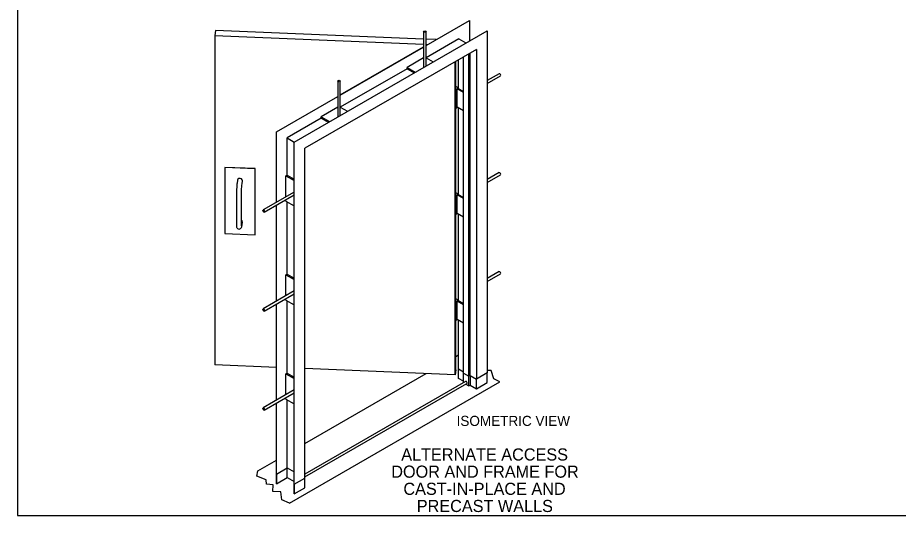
# Model space of a CAD drawing. Extents: x 99862 to 103151, y 100000 to 105076.
# Drawn here: x 99862 to 101604, y 100000 to 100986 of the extents above; entities that cross this region are included whole.
import ezdxf

# ---------------------------------------------------------------- set-up
doc = ezdxf.new("R2010")
doc.units = 0
for name, color, linetype in [('Level 1', 7, 'Continuous'), ('Level 18', 7, 'Continuous'), ('Level 20', 7, 'Continuous'), ('Level 5', 7, 'Continuous'), ('Level 60', 7, 'Continuous')]:
    doc.layers.add(name, color=color, linetype=linetype)

msp = doc.modelspace()

# ---------------------------------------------------------------- linework, layer by layer
at = {"layer": 'Level 1'}
for p, q in [((100395.1, 100673.5), (100392.6, 100672.1)), ((100373.9, 100227.7), (100373.9, 100418)), ((100374.2, 100227.9), (100374.2, 100418.2)), ((100392.6, 100426.1), (100392.6, 100428.8)), ((100392.6, 100426.1), (100408.9, 100416.7)), ((100373.9, 100081.6), (100373.9, 100221.9)), ((100374.2, 100081.4), (100374.2, 100222.1)), ((100409.2, 100061.2), (100430.4, 100073.5)), ((100408.9, 100061.4), (100409.2, 100061.2))]:
    msp.add_line(p, q, dxfattribs=at)
msp.add_lwpolyline([(99862, 99999.5), (103151, 99999.5), (103151, 102075.5), (99862, 102075.5)], close=True, dxfattribs=at)
at = {"layer": 'Level 18'}
for p, q in [((100670.2, 100930.4), (100755.7, 100979.8)), ((100670.2, 100930), (100756, 100979.6)), ((100756, 100979.6), (100755.7, 100979.8)), ((100756, 100979.6), (100756, 100939.6)), ((100253.2, 100960), (100252, 100949.9)), ((100665.2, 100942.9), (100253.2, 100960)), ((100408.9, 100739.1), (100790.7, 100959.6)), ((100409.2, 100738.9), (100791, 100959.4)), ((100665.2, 100957.9), (100665.2, 100887.1)), ((100670.2, 100890), (100670.2, 100957.9)), ((100790.7, 100959.6), (100791, 100959.4)), ((100791, 100959.4), (100791, 100281.7)), ((100252, 100949.9), (100665.2, 100932.8)), ((100252, 100949.9), (100252, 100297.8)), ((100735.2, 100943.4), (100670.2, 100905.9)), ((100690.1, 100941.9), (100670.2, 100942.7)), ((100735.2, 100943.4), (100749, 100935.5)), ((100769.8, 100922.6), (100430.4, 100726.7)), ((100500.4, 100832.4), (100665.2, 100927.5)), ((100500.4, 100832), (100665.2, 100927.1)), ((100670.2, 100932.6), (100673.7, 100932.4)), ((100769.8, 100922.6), (100769.8, 100269.4)), ((100665.2, 100905.9), (100632.4, 100887)), ((100670.2, 100906), (100684, 100898)), ((100744.2, 100281.2), (100744.2, 100907.8)), ((100754.8, 100275), (100754.8, 100913.9)), ((100757.5, 100276.6), (100757.5, 100915.5)), ((100727.5, 100278), (100727.5, 100898.2)), ((100728.8, 100288.1), (100728.8, 100898.9)), ((100734.5, 100845.1), (100734.5, 100902.2)), ((100632.4, 100884.1), (100500.4, 100807.9)), ((100632.4, 100884.1), (100632.4, 100887)), ((100632.4, 100887), (100648.7, 100877.6)), ((100632.4, 100884.1), (100646.2, 100876.1)), ((100814.9, 100874.4), (100791, 100860.6)), ((100495.4, 100859.9), (100495.4, 100789.1)), ((100500.4, 100792), (100500.4, 100859.9)), ((100791, 100854.8), (100817.4, 100870)), ((100728.8, 100843.9), (100727.5, 100833.3)), ((100744.2, 100837.4), (100731.8, 100844.5)), ((100731.8, 100807.8), (100731.8, 100844.5)), ((100732.9, 100846), (100744.2, 100839.4)), ((100373.9, 100759.3), (100495.4, 100829.5)), ((100374.2, 100759.1), (100495.4, 100829.1)), ((100495.4, 100807.9), (100462.7, 100789)), ((100500.4, 100808), (100514.3, 100800)), ((100728.9, 100807.3), (100727.5, 100796.5)), ((100744.2, 100800.7), (100731.8, 100807.8)), ((100734.5, 100634.8), (100734.5, 100806.3)), ((100462.8, 100786.2), (100395.1, 100747.1)), ((100462.7, 100789), (100479, 100779.6)), ((100462.7, 100786.1), (100462.7, 100789)), ((100462.7, 100786.3), (100476.6, 100778.2)), ((100373.9, 100619.7), (100373.9, 100759.3)), ((100374.2, 100759.1), (100373.9, 100759.3)), ((100374.2, 100619.9), (100374.2, 100759.1)), ((100395.1, 100747.1), (100408.9, 100739.1)), ((100395.1, 100673.5), (100395.1, 100747.1)), ((100408.9, 100061.4), (100408.9, 100739.1)), ((100408.9, 100739.1), (100409.2, 100738.9)), ((100409.2, 100061.2), (100409.2, 100738.9)), ((100430.4, 100073.5), (100430.4, 100726.7)), ((100271.9, 100688.6), (100271.9, 100688.9)), ((100331.8, 100686.4), (100271.9, 100688.9)), ((100271.9, 100688.6), (100271.9, 100557.9)), ((100331.7, 100686.1), (100271.9, 100688.6)), ((100331.7, 100686.1), (100331.8, 100686.4)), ((100331.7, 100555.5), (100331.7, 100686.1)), ((100331.8, 100555.7), (100331.8, 100686.4)), ((100296.9, 100663.5), (100296.1, 100657.7)), ((100306.1, 100656.5), (100306.8, 100662.2)), ((100392.6, 100672.1), (100408.9, 100662.7)), ((100392.6, 100630.5), (100392.6, 100672.1)), ((100395.1, 100673.5), (100408.9, 100665.5)), ((100814.9, 100678.4), (100791, 100664.6)), ((100791, 100658.9), (100817.4, 100674.1)), ((100294.7, 100629.2), (100294.7, 100580.2)), ((100304.7, 100580.2), (100304.7, 100629.2)), ((100408.9, 100639.9), (100347.5, 100604.5)), ((100350, 100600.2), (100408.9, 100634.2)), ((100728.9, 100633.8), (100727.5, 100623)), ((100744.2, 100627.2), (100731.8, 100634.3)), ((100731.8, 100597.6), (100731.8, 100634.3)), ((100732.9, 100635.7), (100744.2, 100629.2)), ((100373.9, 100423.8), (100373.9, 100614)), ((100374.2, 100424), (100374.2, 100614.2)), ((100392.6, 100622.1), (100392.6, 100624.8)), ((100392.6, 100622.1), (100408.9, 100612.7)), ((100395.1, 100477.6), (100395.1, 100620.6)), ((100728.9, 100597.1), (100727.5, 100586.3)), ((100744.2, 100590.4), (100731.8, 100597.6)), ((100734.5, 100424.6), (100734.5, 100596)), ((100306.1, 100574.8), (100306.8, 100580.6)), ((100271.9, 100557.9), (100331.7, 100555.5)), ((100331.7, 100555.5), (100331.8, 100555.7)), ((100395.1, 100477.6), (100392.6, 100476.1)), ((100392.6, 100476.1), (100408.9, 100466.7)), ((100392.6, 100434.6), (100392.6, 100476.1)), ((100395.1, 100477.6), (100408.9, 100469.6)), ((100814.9, 100482.3), (100791, 100468.5)), ((100791, 100462.8), (100817.4, 100478)), ((100408.9, 100444), (100347.5, 100408.6)), ((100350, 100404.2), (100408.9, 100438.2)), ((100395.1, 100281.4), (100395.1, 100424.7)), ((100728.9, 100423.6), (100727.5, 100412.8)), ((100744.2, 100416.9), (100731.8, 100424)), ((100731.8, 100387.3), (100731.8, 100424)), ((100732.9, 100425.5), (100744.2, 100418.9)), ((100728.9, 100386.8), (100727.5, 100376)), ((100744.2, 100380.2), (100731.8, 100387.3)), ((100734.5, 100289.8), (100734.5, 100385.8)), ((100373.9, 100292.7), (100252, 100297.8)), ((100395.1, 100281.4), (100392.6, 100280)), ((100392.6, 100280), (100408.9, 100270.6)), ((100392.6, 100238.5), (100392.6, 100280)), ((100395.1, 100281.4), (100408.9, 100273.5)), ((100727.5, 100278), (100430.4, 100290.4)), ((100728.8, 100288.1), (100727.5, 100278)), ((100734.5, 100289.8), (100744.2, 100284.2)), ((100744.2, 100281.2), (100754.8, 100275)), ((100744.2, 100262.5), (100744.2, 100281.2)), ((100791, 100281.7), (100769.8, 100269.4)), ((100791, 100262.6), (100791, 100281.7)), ((100748.3, 100264.9), (100430.4, 100081.3)), ((100430.4, 100075.6), (100750.8, 100260.5)), ((100757.5, 100276.6), (100754.8, 100275)), ((100754.8, 100256), (100754.8, 100275)), ((100757.5, 100276.6), (100769.8, 100269.4)), ((100757.5, 100276.6), (100757.5, 100257.5)), ((100769.8, 100250.3), (100769.8, 100269.4)), ((100408.9, 100247.9), (100347.5, 100212.4)), ((100350, 100208.1), (100408.9, 100242.1)), ((100392.6, 100230), (100392.6, 100232.7)), ((100392.6, 100230), (100408.9, 100220.6)), ((100395.1, 100093.5), (100395.1, 100228.6)), ((100374.2, 100081.4), (100395.1, 100093.5)), ((100395.1, 100093.5), (100408.9, 100085.5)), ((100395.1, 100074.4), (100395.1, 100093.5)), ((100373.9, 100081.6), (100374.2, 100081.4)), ((100374.2, 100062.3), (100374.2, 100081.4)), ((100374.2, 100062.3), (100395.1, 100074.4)), ((100395.1, 100074.4), (100408.9, 100066.4)), ((100409.2, 100061.2), (100430.4, 100073.5)), ((100430.4, 100054.4), (100430.4, 100073.5)), ((100408.9, 100061.4), (100409.2, 100061.2)), ((100409.2, 100042.1), (100409.2, 100061.2)), ((100409.2, 100042.1), (100430.4, 100054.4))]:
    msp.add_line(p, q, dxfattribs=at)
for points in [[(100744.2, 100265.1), (100734.5, 100270.8), (100734.5, 100289.8)], [(100748.8, 100259.4), (100754.8, 100256), (100757.5, 100257.5), (100769.8, 100250.3), (100791, 100262.6)], [(100373.9, 100081.6), (100373.9, 100062.5), (100374.2, 100062.3)], [(100408.9, 100061.4), (100408.9, 100042.3), (100409.2, 100042.1)]]:
    msp.add_lwpolyline(points, dxfattribs=at)
for centre, major_axis in [((100667.7, 100957.9), (-2.5, 0)), ((100497.9, 100859.9), (-2.5, 0)), ((100348.8, 100602.4), (-1.25, 2.17)), ((100348.8, 100406.4), (-1.25, 2.17)), ((100348.8, 100210.3), (-1.25, 2.17))]:
    msp.add_ellipse(centre, major_axis=major_axis, ratio=0.57735, dxfattribs=at)
for centre, major_axis, ratio, start_param, end_param in [((100816.1, 100872.2), (-1.25, 2.17), 0.57735, 3.141593, 6.283185), ((100729.2, 100846.1), (3.75, 0), 0.57735, 6.227515, 7.962179), ((100729.2, 100846.1), (3.75, 0), 0.57735, 4.623664, 6.227515), ((100729.2, 100809.3), (3.75, 0), 0.57735, 4.623664, 5.497787), ((100816.1, 100676.2), (-1.25, 2.17), 0.57735, 3.141593, 6.283185), ((100301.8, 100662.8), (4.96, -0.62), 0.814396, 6.283146, 9.424778), ((100299.7, 100629.2), (5, 0), 0.57735, 6.211436, 6.283188), ((100729.2, 100635.8), (3.75, 0), 0.57735, 6.227515, 7.962179), ((100729.2, 100635.8), (3.75, 0), 0.57735, 4.627769, 5.497787), ((100729.2, 100635.8), (3.75, 0), 0.57735, 5.497787, 6.227515), ((100729.2, 100599.1), (3.75, 0), 0.57735, 4.623664, 5.497787), ((100301.8, 100581.2), (4.96, -0.62), 0.814396, 6.283185, 7.346876), ((100299.7, 100580.2), (5, 0), 0.57735, 6.211436, 6.283185), ((100816.1, 100480.1), (-1.25, 2.17), 0.57735, 3.141593, 6.283185), ((100729.2, 100425.6), (3.75, 0), 0.57735, 6.227515, 7.962179), ((100729.2, 100425.6), (3.75, 0), 0.57735, 4.627769, 5.497787), ((100729.2, 100425.6), (3.75, 0), 0.57735, 5.497787, 6.227515), ((100729.2, 100388.8), (3.75, 0), 0.57735, 4.623664, 5.497787), ((100749.5, 100262.7), (-1.25, 2.17), 0.57735, 3.141569, 6.283185)]:
    msp.add_ellipse(centre, major_axis=major_axis, ratio=ratio, start_param=start_param, end_param=end_param, dxfattribs=at)
for points in [[(100296.1, 100657.7), (100295.8, 100655.2), (100295.1, 100646.2), (100294.7, 100634.5), (100294.7, 100629.2)], [(100304.7, 100629.2), (100304.7, 100632.5), (100304.9, 100642.7), (100305.6, 100653), (100306.1, 100656.5)], [(100294.7, 100580.2), (100294.7, 100577.1), (100294.8, 100573.7), (100295.1, 100571.5), (100295.5, 100569.8), (100297, 100567.5), (100300.2, 100566.4), (100303.5, 100567.5), (100305.3, 100570.1), (100305.6, 100571.9), (100306, 100573.5), (100306.1, 100574.8)], [(100304.9, 100573.3), (100304.9, 100573.3), (100304.8, 100574.2), (100304.7, 100577.1), (100304.7, 100580.2)]]:
    msp.add_open_spline(points, degree=3, dxfattribs=at)
at = {"layer": 'Level 5'}
for p, q in [((100728.8, 100314.2), (100734.5, 100317.5)), ((100430.4, 100141.9), (100670.3, 100280.4)), ((100399.8, 100023.8), (100815.9, 100264)), ((100337.2, 100088.1), (100373.9, 100109.2))]:
    msp.add_line(p, q, dxfattribs=at)
for points in [[(100815.9, 100264), (100804, 100270.1), (100799.1, 100286.3), (100791, 100286.7)], [(100399.8, 100023.8), (100384.9, 100030.5), (100382.9, 100046.1), (100366.8, 100046.8), (100367.5, 100059.9), (100354.5, 100061.1), (100353.4, 100069.8), (100335.3, 100077.2), (100337.2, 100088.1)]]:
    msp.add_lwpolyline(points, dxfattribs=at)
at = {"layer": 'Level 60'}
msp.add_line((99862, 99999.5), (99862, 99999.5), dxfattribs=at)

# ---------------------------------------------------------------- texts
at = {"layer": 'Level 20'}
for s, height, p in [('ISOMETRIC VIEW', 20, (100730.5, 100176.7)), ('ALTERNATE ACCESS', 24, (100620.9, 100108.2)), ('DOOR AND FRAME FOR', 24, (100601.2, 100074.2)), ('CAST-IN-PLACE AND', 24, (100625.2, 100040.2)), ('PRECAST WALLS', 24, (100651.7, 100006.2))]:
    msp.add_text(s, height=height, dxfattribs=at).set_placement(p)

doc.saveas('drawing.dxf')
